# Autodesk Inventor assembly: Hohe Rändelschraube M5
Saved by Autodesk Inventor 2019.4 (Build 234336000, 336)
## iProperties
Created: 2021-06
Part Number: Hohe Rändelschraube M5
Document SubType Name: Assembly
Designer: Administrator
Title: Hohe Rändelschraube M5 v2
Author: Administrator
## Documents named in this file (2)
- c:\worker\convert-fusion-r04\tmp\job-1\39\output\files\e1e84fd7-b652-4e3d-a1c7-f0a54bbc30a7\Hohe Rändelschraube M5 v2.iam
- c:\worker\convert-fusion-r04\tmp\job-1\39\output\files\e1e84fd7-b652-4e3d-a1c7-f0a54bbc30a7\_Knurled screw DIN 464-M5-12-ZB.ipt
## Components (1 placed, 1 different names)
1. _Knurled screw DIN 464-M5-12-ZB:1
